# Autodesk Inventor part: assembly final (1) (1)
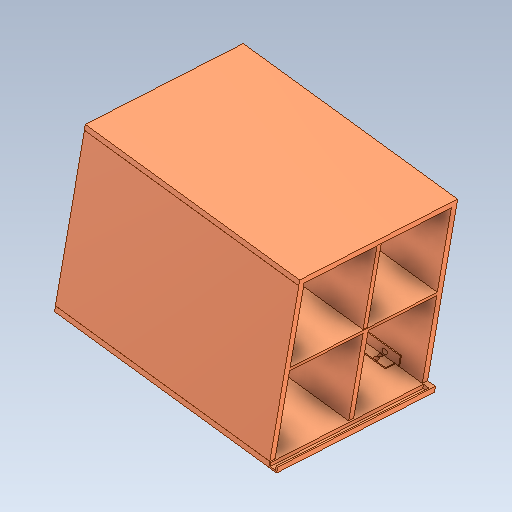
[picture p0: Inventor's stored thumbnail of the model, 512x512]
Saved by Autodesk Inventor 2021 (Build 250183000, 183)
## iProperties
Created: 2021-07
Part Number: assembly final (1) (1)
Material: Generic
Document SubType Name: Modeling
Designer: TARUN
Density: 1 g/cm^3
Appearance: Default
Author: TARUN
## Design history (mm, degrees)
feature "Base1"
body "Solid1"
